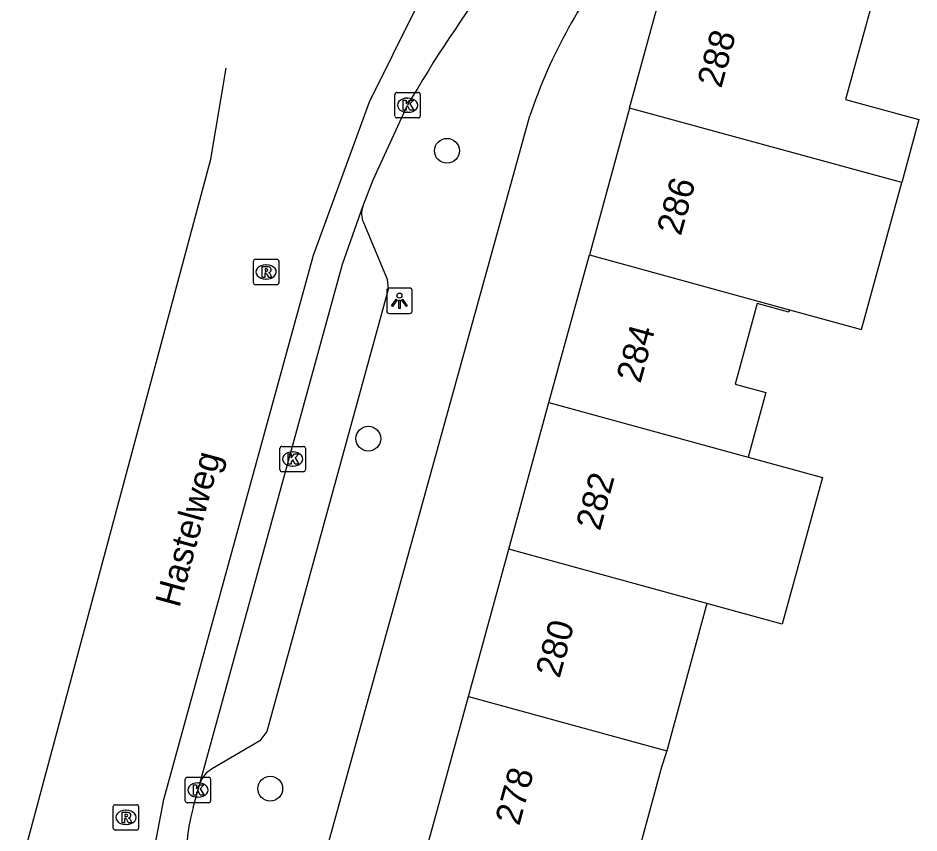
# Model space of a CAD drawing. Extents: x 158087 to 159494, y 382905 to 383981.
# Drawn here: x 158111.3 to 158146.8, y 383168.66 to 383200.77 of the extents above; entities that cross this region are included whole.
import ezdxf

# ---------------------------------------------------------------- set-up
doc = ezdxf.new("R2010")
doc.units = 0
for name, color, linetype in [('IMGEO_Boom', 7, 'Continuous'), ('IMGEO_Kolk', 7, 'Continuous'), ('IMGEO_Lichtpunt', 7, 'Continuous'), ('IMGEO_Openbare_ruimte_label', 7, 'Continuous'), ('IMGEO_Pand', 7, 'Continuous'), ('IMGEO_Pand_nummerreeks', 7, 'Continuous'), ('IMGEO_Rijbaan_lokaal_gesloten', 7, 'Continuous'), ('IMGEO_Rioolput', 7, 'Continuous'), ('IMGEO_Voetpad_open', 7, 'Continuous')]:
    doc.layers.add(name, color=color, linetype=linetype)

msp = doc.modelspace()

# ---------------------------------------------------------------- linework, layer by layer
at = {"layer": 'IMGEO_Boom'}
for centre in [(158128.198, 383195.54), (158125.102, 383184.199), (158121.236, 383170.41)]:
    msp.add_circle(centre, 0.489, dxfattribs=at)
at = {"layer": 'IMGEO_Kolk'}
for p, q in [((158126.222, 383197.838), (158127.074, 383197.838)), ((158126.147, 383196.912), (158126.147, 383197.764)), ((158126.635, 383197.618), (158126.66, 383197.618)), ((158127.148, 383197.764), (158127.148, 383196.912)), ((158127.074, 383196.838), (158126.222, 383196.838)), ((158126.658, 383197.058), (158126.633, 383197.058)), ((158121.62, 383182.97), (158121.62, 383183.822)), ((158121.695, 383183.896), (158122.547, 383183.896)), ((158122.108, 383183.676), (158122.133, 383183.676)), ((158122.621, 383183.822), (158122.621, 383182.97)), ((158122.547, 383182.896), (158121.695, 383182.896)), ((158122.131, 383183.116), (158122.106, 383183.116)), ((158117.962, 383170.858), (158118.814, 383170.858)), ((158117.887, 383169.932), (158117.887, 383170.784)), ((158118.375, 383170.638), (158118.4, 383170.638)), ((158118.888, 383170.784), (158118.888, 383169.932)), ((158118.814, 383169.858), (158117.962, 383169.858)), ((158118.398, 383170.078), (158118.373, 383170.078))]:
    msp.add_line(p, q, dxfattribs=at)
for points in [[(158126.222, 383197.838), (158127.074, 383197.838)], [(158126.147, 383196.912), (158126.147, 383197.764)], [(158126.468, 383197.538), (158126.591, 383197.538), (158126.591, 383197.387), (158126.721, 383197.538), (158126.885, 383197.538), (158126.739, 383197.387), (158126.892, 383197.138), (158126.74, 383197.138), (158126.655, 383197.302), (158126.591, 383197.235), (158126.591, 383197.138), (158126.468, 383197.138), (158126.468, 383197.538)], [(158127.148, 383197.764), (158127.148, 383196.912)], [(158127.074, 383196.838), (158126.222, 383196.838)], [(158121.62, 383182.97), (158121.62, 383183.822)], [(158121.695, 383183.896), (158122.547, 383183.896)], [(158121.941, 383183.596), (158122.064, 383183.596), (158122.064, 383183.445), (158122.194, 383183.596), (158122.358, 383183.596), (158122.212, 383183.445), (158122.365, 383183.196), (158122.213, 383183.196), (158122.128, 383183.36), (158122.064, 383183.293), (158122.064, 383183.196), (158121.941, 383183.196), (158121.941, 383183.596)], [(158122.621, 383183.822), (158122.621, 383182.97)], [(158122.547, 383182.896), (158121.695, 383182.896)], [(158117.962, 383170.858), (158118.814, 383170.858)], [(158117.887, 383169.932), (158117.887, 383170.784)], [(158118.208, 383170.558), (158118.331, 383170.558), (158118.331, 383170.407), (158118.461, 383170.558), (158118.625, 383170.558), (158118.479, 383170.407), (158118.632, 383170.158), (158118.48, 383170.158), (158118.395, 383170.322), (158118.331, 383170.255), (158118.331, 383170.158), (158118.208, 383170.158), (158118.208, 383170.558)], [(158118.888, 383170.784), (158118.888, 383169.932)], [(158118.814, 383169.858), (158117.962, 383169.858)]]:
    msp.add_lwpolyline(points, dxfattribs=at)
for centre, start, end in [((158126.224, 383197.762), 91.552, 178.448), ((158126.224, 383197.762), 91.552, 178.448), ((158127.072, 383197.762), 1.552, 88.448), ((158127.072, 383197.762), 1.552, 88.448), ((158126.224, 383196.914), 181.552, 268.448), ((158126.224, 383196.914), 181.552, 268.448), ((158127.072, 383196.914), 271.552, 358.448), ((158127.072, 383196.914), 271.552, 358.448), ((158121.697, 383183.82), 91.552, 178.448), ((158121.697, 383183.82), 91.552, 178.448), ((158122.545, 383183.82), 1.552, 88.448), ((158122.545, 383183.82), 1.552, 88.448), ((158121.697, 383182.972), 181.552, 268.448), ((158121.697, 383182.972), 181.552, 268.448), ((158122.545, 383182.972), 271.552, 358.448), ((158122.545, 383182.972), 271.552, 358.448), ((158117.964, 383170.782), 91.552, 178.448), ((158117.964, 383170.782), 91.552, 178.448), ((158118.812, 383170.782), 1.552, 88.448), ((158118.812, 383170.782), 1.552, 88.448), ((158117.964, 383169.934), 181.552, 268.448), ((158117.964, 383169.934), 181.552, 268.448), ((158118.812, 383169.934), 271.552, 358.448), ((158118.812, 383169.934), 271.552, 358.448)]:
    msp.add_arc(centre, 0.0765, start, end, dxfattribs=at)
for centre, major_axis, ratio, start_param, end_param in [((158126.634, 383197.338), (-0.387, 0.002), 0.722429, 4.712389, 7.853982), ((158126.659, 383197.338), (-0.39, 0.002), 0.717154, 1.570796, 4.712389), ((158122.107, 383183.396), (-0.387, 0.002), 0.722429, 4.712389, 7.853982), ((158122.132, 383183.396), (-0.39, 0.002), 0.717154, 1.570796, 4.712389), ((158118.374, 383170.358), (-0.387, 0.002), 0.722429, 4.712389, 7.853982), ((158118.399, 383170.358), (-0.39, 0.002), 0.717154, 1.570796, 4.712389)]:
    msp.add_ellipse(centre, major_axis=major_axis, ratio=ratio, start_param=start_param, end_param=end_param, dxfattribs=at)
at = {"layer": 'IMGEO_Lichtpunt'}
for p, q in [((158125.826, 383190.036), (158125.826, 383189.229)), ((158125.826, 383190.036), (158125.826, 383189.229)), ((158126.728, 383190.131), (158125.92, 383190.131)), ((158126.728, 383190.131), (158125.92, 383190.131)), ((158126.822, 383189.229), (158126.822, 383190.036)), ((158126.822, 383189.229), (158126.822, 383190.036)), ((158125.92, 383189.135), (158126.728, 383189.135)), ((158125.92, 383189.135), (158126.728, 383189.135))]:
    msp.add_line(p, q, dxfattribs=at)
for points in [[(158126.2, 383189.7), (158126.239, 383189.672), (158126.051, 383189.41), (158126.013, 383189.437), (158126.2, 383189.7)], [(158126.302, 383189.652), (158126.349, 383189.652), (158126.349, 383189.33), (158126.302, 383189.33), (158126.302, 383189.652)], [(158126.412, 383189.672), (158126.45, 383189.699), (158126.637, 383189.437), (158126.598, 383189.409), (158126.412, 383189.672)]]:
    msp.add_lwpolyline(points, dxfattribs=at)
msp.add_circle((158126.325, 383189.834), 0.0994, dxfattribs=at)
for centre, start, end in [((158125.92, 383190.036), 90, 180), ((158125.92, 383190.036), 90, 180), ((158126.728, 383190.036), 0, 90), ((158126.728, 383190.036), 0, 90), ((158125.92, 383189.229), 180, 270), ((158125.92, 383189.229), 180, 270), ((158126.728, 383189.229), 270, 0), ((158126.728, 383189.229), 270, 360)]:
    msp.add_arc(centre, 0.0946, start, end, dxfattribs=at)
at = {"layer": 'IMGEO_Pand'}
for points in [[(158135.396, 383197.227), (158136.998, 383203.073), (158140.384, 383202.146), (158141.177, 383205.04), (158145.614, 383203.826), (158143.901, 383197.567), (158146.795, 383196.776), (158146.115, 383194.289)], [(158135.396, 383197.227), (158133.81, 383191.437)], [(158146.115, 383194.289), (158135.396, 383197.227)], [(158141.69, 383189.278), (158144.532, 383188.501), (158146.115, 383194.289)], [(158132.217, 383185.624), (158133.81, 383191.437)], [(158133.81, 383191.437), (158141.69, 383189.278)], [(158141.69, 383189.278), (158141.663, 383189.18), (158140.426, 383189.519), (158139.557, 383186.348), (158140.763, 383186.017), (158140.066, 383183.473)], [(158130.633, 383179.84), (158132.217, 383185.624)], [(158132.217, 383185.624), (158140.066, 383183.473)], [(158140.066, 383183.473), (158142.994, 383182.671), (158141.406, 383176.886), (158138.441, 383177.7)], [(158129.043, 383174.04), (158130.633, 383179.84)], [(158138.441, 383177.7), (158136.43, 383178.251), (158130.633, 383179.84)], [(158138.441, 383177.7), (158137.559, 383174.463), (158136.856, 383171.899)], [(158130.42, 383162.036), (158131.785, 383167.017), (158127.445, 383168.206), (158129.043, 383174.04)], [(158129.043, 383174.04), (158136.856, 383171.899)], [(158136.856, 383171.899), (158136.823, 383171.777), (158136.657, 383171.255), (158135.955, 383168.694), (158135.236, 383166.071), (158133.867, 383161.076)]]:
    msp.add_lwpolyline(points, dxfattribs=at)
at = {"layer": 'IMGEO_Rijbaan_lokaal_gesloten'}
for points in [[(158123.545, 383158.624), (158121.299, 383159.472), (158120.511, 383159.893), (158119.732, 383160.433), (158118.989, 383161.105), (158118.281, 383161.896), (158117.694, 383162.772), (158117.166, 383163.887), (158116.819, 383164.93), (158116.651, 383166.022), (158116.603, 383167.245), (158116.699, 383168.192), (158117.038, 383169.988), (158122.934, 383191.435), (158125.143, 383197.468), (158128.824, 383204.89)], [(158114.447, 383157.32), (158113.975, 383157.813), (158113.174, 383158.889), (158112.421, 383160.267), (158111.855, 383161.854), (158111.404, 383163.963), (158111.299, 383165.033), (158111.383, 383166.817), (158111.593, 383168.013), (158118.896, 383195.213), (158119.498, 383198.799)], [(158124.881, 383193.345), (158125.29, 383194.403), (158126.648, 383197.338)], [(158118.475, 383170.654), (158124.08, 383191.076), (158124.881, 383193.345)], [(158118.195, 383169.67), (158118.475, 383170.654)]]:
    msp.add_lwpolyline(points, dxfattribs=at)
for centre, radius, start, end in [((158170.784, 383171.834), 50.975, 142.9358, 149.9784), ((158126.058, 383167.594), 8.132, 165.2065, 248.5444)]:
    msp.add_arc(centre, radius, start, end, dxfattribs=at)
at = {"layer": 'IMGEO_Rioolput'}
for p, q in [((158120.574, 383190.34), (158120.574, 383191.192)), ((158120.649, 383191.266), (158121.501, 383191.266)), ((158121.062, 383191.046), (158121.087, 383191.046)), ((158121.575, 383191.192), (158121.575, 383190.34)), ((158121.085, 383190.486), (158121.06, 383190.486)), ((158121.501, 383190.266), (158120.649, 383190.266)), ((158115.124, 383169.777), (158115.976, 383169.777)), ((158115.049, 383168.851), (158115.049, 383169.703)), ((158115.537, 383169.557), (158115.562, 383169.557)), ((158116.05, 383169.703), (158116.05, 383168.851)), ((158115.976, 383168.777), (158115.124, 383168.777)), ((158115.56, 383168.997), (158115.535, 383168.997))]:
    msp.add_line(p, q, dxfattribs=at)
for points in [[(158120.574, 383190.34), (158120.574, 383191.192)], [(158120.649, 383191.266), (158121.501, 383191.266)], [(158121.575, 383191.192), (158121.575, 383190.34)], [(158121.163, 383190.964), (158120.911, 383190.966), (158120.911, 383190.566)], [(158120.911, 383190.566), (158121.035, 383190.566), (158121.035, 383190.728), (158121.046, 383190.728)], [(158121.089, 383190.885), (158121.035, 383190.885), (158121.035, 383190.804)], [(158121.035, 383190.804), (158121.087, 383190.804)], [(158121.093, 383190.699), (158121.164, 383190.566), (158121.304, 383190.566), (158121.239, 383190.692)], [(158121.501, 383190.266), (158120.649, 383190.266)], [(158115.124, 383169.777), (158115.976, 383169.777)], [(158115.049, 383168.851), (158115.049, 383169.703)], [(158115.638, 383169.475), (158115.386, 383169.477), (158115.386, 383169.077)], [(158115.564, 383169.396), (158115.51, 383169.396), (158115.51, 383169.315)], [(158116.05, 383169.703), (158116.05, 383168.851)], [(158115.386, 383169.077), (158115.51, 383169.077), (158115.51, 383169.239), (158115.521, 383169.239)], [(158115.51, 383169.315), (158115.562, 383169.315)], [(158115.568, 383169.21), (158115.639, 383169.077), (158115.779, 383169.077), (158115.714, 383169.203)], [(158115.976, 383168.777), (158115.124, 383168.777)]]:
    msp.add_lwpolyline(points, dxfattribs=at)
for centre, radius, start, end in [((158120.651, 383191.19), 0.0765, 91.552, 178.448), ((158120.651, 383191.19), 0.0765, 91.552, 178.448), ((158121.499, 383191.19), 0.0765, 1.552, 88.448), ((158121.499, 383191.19), 0.0765, 1.552, 88.448), ((158121.045, 383190.675), 0.0533, 26.0293, 88.6989), ((158121.071, 383190.993), 0.19, 274.7715, 282.9687), ((158121.095, 383190.789), 0.0964, 77.0061, 93.1865), ((158121.109, 383190.846), 0.0378, 276.6634, 79.6772), ((158121.162, 383190.854), 0.109, 350.3612, 89.416), ((158121.16, 383190.854), 0.112, 277.5842, 350.9817), ((158121.144, 383190.639), 0.108, 29.5134, 73.7905), ((158120.651, 383190.342), 0.0765, 181.552, 268.448), ((158120.651, 383190.342), 0.0765, 181.552, 268.448), ((158121.499, 383190.342), 0.0765, 271.552, 358.448), ((158121.499, 383190.342), 0.0765, 271.552, 358.448), ((158115.126, 383169.701), 0.0765, 91.552, 178.448), ((158115.126, 383169.701), 0.0765, 91.552, 178.448), ((158115.974, 383169.701), 0.0765, 1.552, 88.448), ((158115.974, 383169.701), 0.0765, 1.552, 88.448), ((158115.57, 383169.3), 0.0964, 77.0061, 93.1865), ((158115.584, 383169.357), 0.0378, 276.6634, 79.6772), ((158115.637, 383169.365), 0.109, 350.3612, 89.416), ((158115.52, 383169.186), 0.0533, 26.0293, 88.6989), ((158115.546, 383169.504), 0.19, 274.7715, 282.9687), ((158115.635, 383169.365), 0.112, 277.5842, 350.9817), ((158115.619, 383169.15), 0.108, 29.5134, 73.7905), ((158115.126, 383168.853), 0.0765, 181.552, 268.448), ((158115.126, 383168.853), 0.0765, 181.552, 268.448), ((158115.974, 383168.853), 0.0765, 271.552, 358.448), ((158115.974, 383168.853), 0.0765, 271.552, 358.448)]:
    msp.add_arc(centre, radius, start, end, dxfattribs=at)
for centre, major_axis, ratio, start_param, end_param in [((158121.061, 383190.766), (-0.387, 0.002), 0.722429, 4.712389, 7.853982), ((158121.086, 383190.766), (-0.39, 0.002), 0.717154, 1.570796, 4.712389), ((158115.536, 383169.277), (-0.387, 0.002), 0.722429, 4.712389, 7.853982), ((158115.561, 383169.277), (-0.39, 0.002), 0.717154, 1.570796, 4.712389)]:
    msp.add_ellipse(centre, major_axis=major_axis, ratio=ratio, start_param=start_param, end_param=end_param, dxfattribs=at)
at = {"layer": 'IMGEO_Voetpad_open'}
for points in [[(158123.046, 383166.519), (158131.469, 383196.918)], [(158124.904, 383192.718), (158125.846, 383190.485), (158125.876, 383190.077), (158121.096, 383172.659), (158120.832, 383172.293), (158118.926, 383171.179)]]:
    msp.add_lwpolyline(points, dxfattribs=at)
for centre, radius, start, end in [((158150.374, 383190.692), 19.904, 139.9318, 161.7716), ((158125.75, 383193.063), 0.914, 162.0162, 202.1854), ((158119.47, 383170.256), 1.071, 120.4898, 158.1819)]:
    msp.add_arc(centre, radius, start, end, dxfattribs=at)

# ---------------------------------------------------------------- texts
at = {"layer": 'IMGEO_Openbare_ruimte_label'}
msp.add_text('Hastelweg', height=1, rotation=74.7549, dxfattribs=at).set_placement((158117.655, 383177.507))
at = {"layer": 'IMGEO_Pand_nummerreeks'}
for s, rotation, p in [('288', 74.6779, (158139.002, 383197.975)), ('286', 74.6793, (158137.41, 383192.161)), ('284', 74.6779, (158135.817, 383186.35)), ('282', 74.6793, (158134.224, 383180.536)), ('280', 74.6793, (158132.634, 383174.73)), ('278', 74.6793, (158131.042, 383168.919))]:
    msp.add_text(s, height=1, rotation=rotation, dxfattribs=at).set_placement(p)

doc.saveas('drawing.dxf')
